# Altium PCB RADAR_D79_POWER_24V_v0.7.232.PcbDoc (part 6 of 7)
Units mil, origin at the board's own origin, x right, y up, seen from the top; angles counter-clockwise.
Board outline 3110.24 x 3110.24 mil, 8 copper layers (Top Layer, GND1, SIG1, PWR1, PWR2, SIG2, GND2, Bottom Layer), stack 55.2 mil thick; 304 components, 269 nets, 1408 pads, 1367 vias.
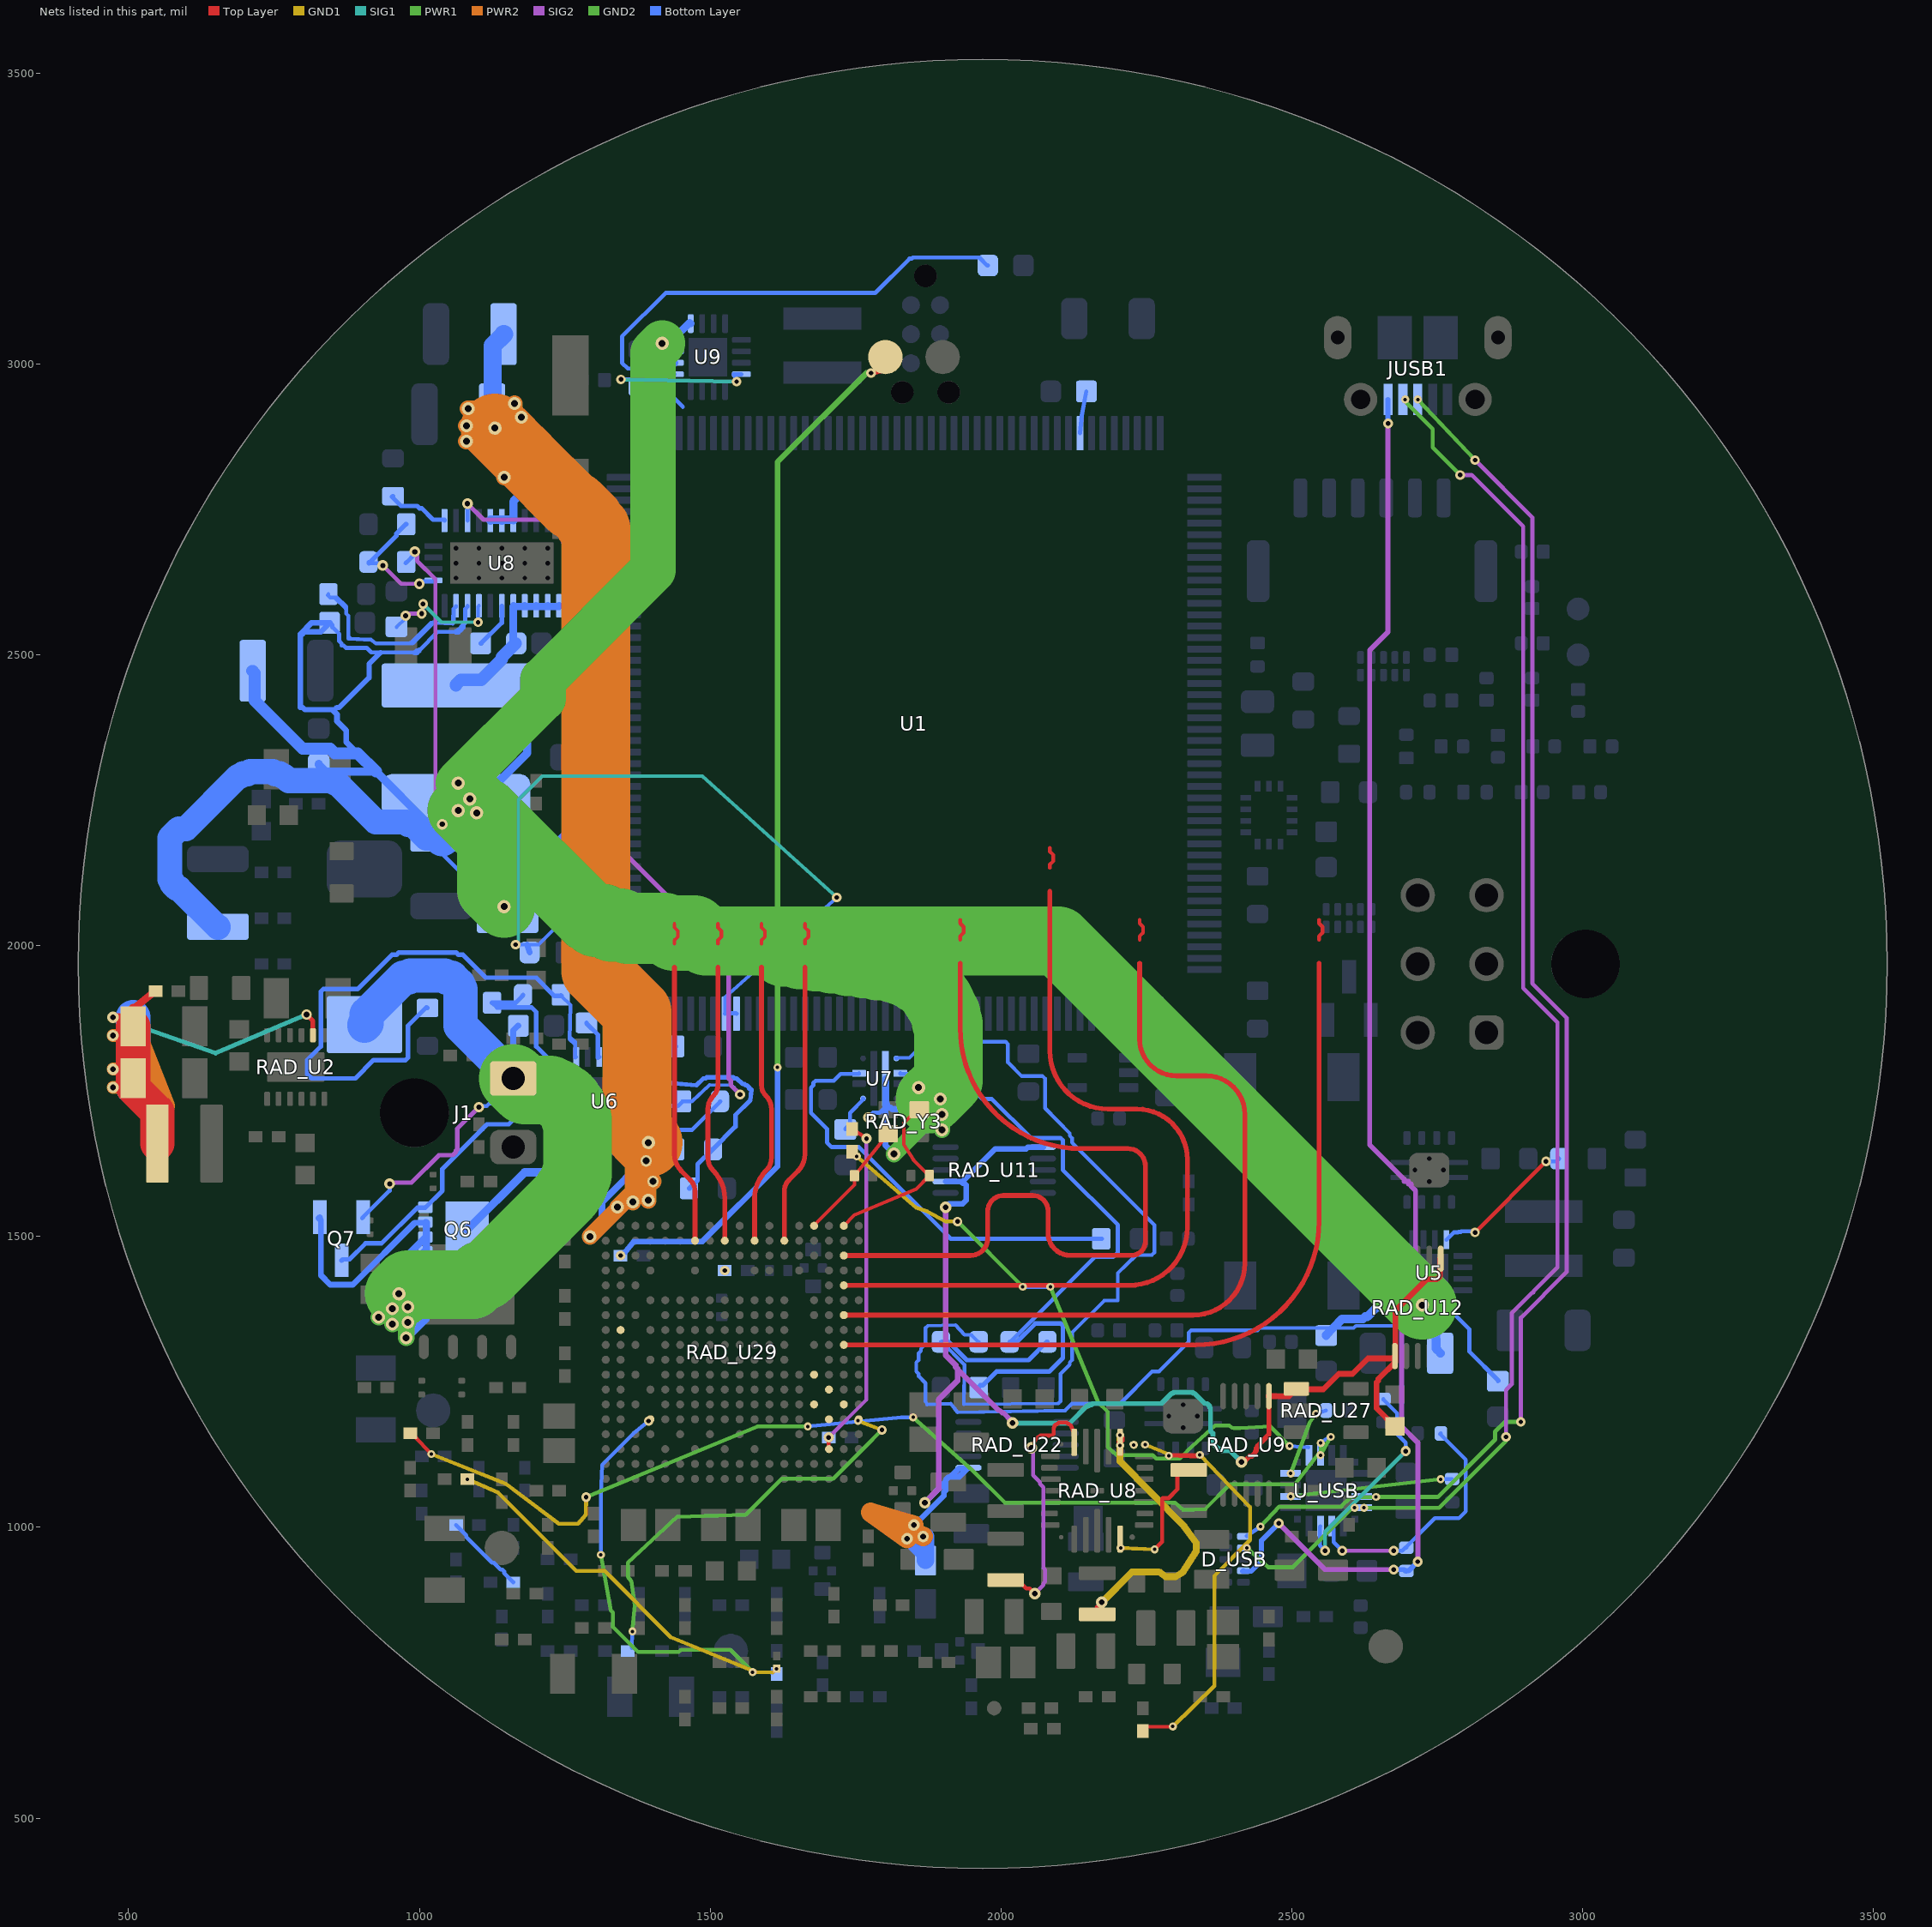
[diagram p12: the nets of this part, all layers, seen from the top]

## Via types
v1: diameter 13.77, hole 5.9, Top Layer to GND1, tented both sides, 393 vias
v2: diameter 16.54, hole 7.87, Top Layer to Bottom Layer, tented both sides, 129 vias
v3: diameter 19.68, hole 9.84, Top Layer to Bottom Layer, tented both sides, 126 vias
v4: diameter 13.77/13.77 (per signal layer), hole 5.9, Top Layer to GND1, tented both sides, 120 vias
v5: diameter 13.77, hole 5.9, Top Layer to GND1, tented top, 104 vias
v6: diameter 13.78, hole 5.91, Top Layer to GND1, tented both sides, 75 vias
v7: diameter 19.68, hole 9.84, Top Layer to Bottom Layer, 74 vias
v8: diameter 17.32, hole 7.87, Top Layer to Bottom Layer, tented both sides, 71 vias
v9: diameter 13.78, hole 5.91, GND2 to Bottom Layer, tented both sides, 64 vias
v10: diameter 13.78, hole 5.91, Top Layer to GND1, tented bottom, 39 vias
v11: diameter 13.78, hole 5.91, GND2 to Bottom Layer, tented top, 38 vias
v12: diameter 13.78, hole 5.91, Top Layer to GND1, 26 vias
v13: diameter 16.54, hole 7.87, GND2 to Bottom Layer, tented both sides, 22 vias
v14: diameter 16.54, hole 7.87, Top Layer to Bottom Layer, 19 vias
v15: diameter 22.05, hole 11.81, Top Layer to Bottom Layer, tented both sides, 17 vias
v16: diameter 13.78, hole 5.91, GND2 to Bottom Layer, 9 vias
v17: diameter 18.11, hole 9.06, Top Layer to Bottom Layer, 7 vias
v18: diameter 22.83, hole 11.81, Top Layer to Bottom Layer, 6 vias
v19: diameter 22.05, hole 11.81, Top Layer to Bottom Layer, 6 vias
v20: diameter 22.83, hole 11.81, Top Layer to Bottom Layer, tented both sides, 5 vias
v21: diameter 19.68, hole 7.87, Top Layer to Bottom Layer, 3 vias
v22: diameter 17.32, hole 8.66, Top Layer to Bottom Layer, 3 vias
v23: diameter 20.47, hole 9.84, Top Layer to Bottom Layer, 3 vias
v24: diameter 17.72, hole 9.84, Top Layer to Bottom Layer, tented both sides, 2 vias
v25: diameter 22.05, hole 11.02, Top Layer to Bottom Layer, 2 vias
v26: diameter 19.68, hole 11.81, Top Layer to Bottom Layer, 2 vias
v27: diameter 18, hole 9.84, Top Layer to Bottom Layer, tented both sides, 1 vias
v28: diameter 18.11, hole 9.06, Top Layer to Bottom Layer, tented both sides, 1 vias

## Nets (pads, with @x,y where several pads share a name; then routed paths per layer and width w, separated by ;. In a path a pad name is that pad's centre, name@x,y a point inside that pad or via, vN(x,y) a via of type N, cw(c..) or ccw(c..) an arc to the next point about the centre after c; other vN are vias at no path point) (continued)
TI_REGOUT_3V3: RAD_C22.2 RAD_C23.1 RAD_C25.1 RAD_C26.1 RAD_C29.1 RAD_C145.1 RAD_L6.2 RAD_R200.1 RAD_U2.8 RAD_U9.6 RAD_U11.2 RAD_U11.6 RAD_U12.1 RAD_U12.6 RAD_U22.6 RAD_U27.1 | length 4299
  Top Layer w8: v27(805.91,1881.42) 816.93,1870.39 RAD_U2.8@816.93,1846.06
  Top Layer w8.66: v3(2413.39,1112.2) 2415.35,1114.17 2419.29,1114.17 2427.17,1122.05 2431.1,1122.05 2437.01,1127.95 2437.01,1129.92 2438.98,1131.89 2438.98,1135.83 2440.94,1137.8 2440.94,1139.76 2460.63,1159.45 RAD_U9.6@2460.63,1225.39 2460.63,1226.38 2460.14,1225.89 RAD_U9.6@2459.65,1225.39
  Top Layer w9.84: RAD_U27.1@2507.87,1238.19 RAD_U27.1@2506.89,1237.2 ; RAD_U12.6@2677.17,1294.29 RAD_U12.6@2678.15,1293.31 ; RAD_U12.1@2755.91,1461.61 2754.92,1461.61 2754.92,1432.09 2749.02,1426.18 2731.3,1426.18 2678.15,1373.03 RAD_U12.6@2678.15,1293.31 ; RAD_U9.6@2460.63,1225.39 2459.65,1225.39 RAD_U9.6@2460.63,1225.39 ; RAD_U9.6@2460.63,1225.39 2495.08,1225.39 RAD_U27.1@2506.89,1237.2 ; RAD_U27.1@2506.89,1237.2 2554.13,1237.2 2580.71,1263.78 2604.33,1263.78 2630.91,1290.35 2675.2,1290.35 RAD_U12.6@2678.15,1293.31 ; RAD_C145.1@2677.17,1173.23 2678.15,1172.24 RAD_C145.1@2677.17,1173.23 ; RAD_C145.1@2677.17,1173.23 2645.67,1204.72 2645.67,1249.02 2648.62,1251.97 2648.62,1254.92 2678.15,1284.45 RAD_U12.6@2678.15,1293.31
  Top Layer w12.6: RAD_C25.1@507.82,1891.04 RAD_C22.2@546.28,1921.91
  Top Layer w13.78: v3(473.03,1756.27) RAD_C29.1@507.82,1756.27 ; v3(473.03,1787.76) RAD_C29.1@507.82,1787.76 ; v3(473.03,1845.37) RAD_C25.1@507.82,1845.37 ; v3(473.03,1876.87) RAD_C25.1@507.82,1876.87
  Top Layer w17.72: RAD_C25.1@507.82,1861.12 507.82,1876.87 RAD_C25.1@507.82,1891.04
  Top Layer w59.06: RAD_C25.1@507.82,1861.12 507.82,1845.37 507.82,1787.76 RAD_C29.1@507.82,1772.02 507.82,1756.27 507.82,1756.15 549.41,1714.57 RAD_L6.2@549.41,1659.68
  PWR2 w21.65: v3(473.03,1756.27) 515.75,1756.27 ; v3(473.03,1787.76) 515.75,1787.76 ; v3(473.03,1845.37) 515.75,1845.37
  PWR2 w33.46: 515.75,1756.27 562.99,1724.41 ; 515.75,1787.76 562.99,1724.41 ; 515.75,1845.37 562.99,1724.41 ; v3(1838.58,980.32) 1835.18,982.76 1775.59,1025.59 ; v3(1850.39,1003.94) 1845.81,1005.27 1775.59,1025.59 ; v3(1866.14,984.25) 1845.67,993.6 1844.82,993.98 1775.59,1025.59
  SIG1 w7.87: v3(473.03,1876.87) 649.61,1814.96 v27(805.91,1881.42)
  SIG1 w8.66: v3(2019.68,1179.13) 2118.11,1179.13 2147.64,1208.66 2149.61,1208.66 2151.57,1210.63 2155.51,1210.63 2157.48,1212.6 2275.59,1212.6 2293.31,1230.32 2295.28,1230.32 2297.24,1232.28 2328.74,1232.28 2330.71,1230.32 2332.68,1230.32 2350.39,1212.6 2354.33,1212.6 2358.27,1208.66 2358.27,1206.69 2360.24,1204.72 2360.24,1165.35 2364.17,1161.42 2364.17,1145.67 2366.14,1143.7 2366.14,1141.73 2372.05,1135.83 2374.02,1135.83 2375.98,1133.86 2377.95,1133.86 2379.92,1131.89 2393.7,1131.89 v3(2413.39,1112.2)
  SIG2 w8.66: 1922.24,1275.59 1921.26,1275.59 1925.2,1271.65 1996.06,1200.79 1998.03,1200.79 2001.97,1196.85 2003.94,1196.85 2017.72,1183.07 2017.72,1181.1 v3(2019.68,1179.13)
  SIG2 w9.84: v7(1869.09,1042.32) 1892.72,1065.94 1892.72,1219.49 1925.2,1251.97 1925.2,1271.65 1925.2,1272.64 1922.24,1275.59 1922.24,1278.54 1904.53,1296.26 v7(1904.53,1550.2)
  Bottom Layer w9.84: v3(1850.39,1003.94) 1851.38,1003.94 1879.43,1031.99 1901.57,1054.13 1901.57,1060.04 1904.53,1062.99 1904.53,1077.76 ; v7(1869.09,1042.32) 1904.53,1077.76 ; v7(1904.53,1550.2) 1910.43,1556.1 1934.06,1556.1 1939.96,1562.01 1939.96,1588.58 1937.01,1591.54 1934.06,1591.54 1931.1,1594.49 ; RAD_U11.2@1904.53,1594.49 1931.1,1594.49 ; RAD_U22.6@1943.9,1102.36 RAD_U22.6@1942.91,1101.38 ; 1904.53,1077.76 1904.53,1080.71 1910.43,1086.61 1913.39,1086.61 ; 1913.39,1086.61 1928.15,1086.61 RAD_U22.6@1942.91,1101.38 ; 1913.39,1086.61 1928.15,1101.38 RAD_U22.6@1942.91,1101.38 ; 1931.1,1594.49 1934.06,1594.49 1990.16,1650.59 2043.31,1650.59 2046.26,1653.54 RAD_U11.6@2071.85,1653.54 ; RAD_U11.6@2071.85,1653.54 2072.83,1653.54 RAD_U11.6@2071.85,1653.54
  Bottom Layer w13.78: v3(473.03,1756.27) RAD_C26.1@507.82,1756.27 ; v3(473.03,1787.76) RAD_C26.1@507.82,1787.76 ; v3(473.03,1845.37) RAD_C23.1@507.82,1845.37 ; v3(473.03,1876.87) RAD_C23.1@507.82,1876.87
  Bottom Layer w21.65: v3(1838.58,980.32) RAD_R200.1@1870.08,948.82 ; v3(1850.39,1003.94) v3@1870.08,984.25 ; v3(1866.14,984.25) v3@1870.08,980.32
  Bottom Layer w29.53: RAD_R200.1@1870.08,942.91 1870.08,948.82 1870.08,980.32 v3@1870.08,984.25
  Bottom Layer w59.06: RAD_C26.1@507.82,1756.27 RAD_C26.1@507.82,1772.02 507.82,1787.76 507.82,1845.37 RAD_C23.1@507.82,1861.12 RAD_C23.1@507.82,1876.87
TI_RX1: RAD_U29.M2 | length 520.8
  Top Layer w6.3: 1438.41,2003.15 1438.41,2009.25 1444.32,2015.16 1444.32,2025.4 1438.41,2031.3 1438.41,2037.4
  Top Layer w8.4: 1438.41,1962.6 1438.41,1850.21 1438.41,1849.22 1438.41,1641.36 ccw(c1479.21,1641.36) 1450.36,1612.51 1465.86,1597.01 cw(c1446.59,1577.74) 1473.85,1577.74 RAD_U29.M2@1473.85,1492.7
TI_RX2: RAD_U29.K2 | length 521.4
  Top Layer w6.3: 1513.22,2003.15 1513.22,2009.25 1519.12,2015.16 1519.12,2025.4 1513.22,2031.3 1513.22,2037.4
  Top Layer w8.4: 1513.22,1962.6 1513.22,1850.21 1513.22,1849.22 1513.22,1760.27 cw(c1487.73,1760.27) 1505.75,1742.24 ccw(c1529.41,1718.59) 1495.95,1718.59 1495.95,1635.46 ccw(c1527.78,1635.46) 1505.27,1612.96 cw(c1457.59,1565.27) 1525.03,1565.27 RAD_U29.K2@1525.03,1492.7
TI_RX3: RAD_U29.H2 | length 521.4
  Top Layer w6.3: 1588.02,2003.15 1588.02,2009.25 1593.93,2015.16 1593.93,2025.4 1588.02,2031.3 1588.02,2037.4
  Top Layer w8.4: RAD_U29.H2@1576.21,1492.7 1576.21,1565.27 cw(c1643.65,1565.27) 1595.96,1612.96 ccw(c1573.46,1635.46) 1605.28,1635.46 1605.28,1718.59 ccw(c1571.83,1718.59) 1595.49,1742.24 cw(c1613.51,1760.27) 1588.02,1760.27 1588.02,1849.22 1588.02,1850.21 1588.02,1962.6
TI_RX4: RAD_U29.F2 | length 520.8
  Top Layer w6.3: 1662.82,2003.15 1662.82,2009.25 1668.73,2015.16 1668.73,2025.4 1662.82,2031.3 1662.82,2037.4
  Top Layer w8.4: RAD_U29.F2@1627.39,1492.7 1627.39,1577.74 cw(c1654.64,1577.74) 1635.37,1597.01 1650.87,1612.51 ccw(c1622.03,1641.36) 1662.82,1641.36 1662.82,1849.22 1662.82,1850.21 1662.82,1962.6
TI_SOP0_TDO: RAD_R310.1 RAD_R386.1 | length 142.7
  Bottom Layer w7.09: RAD_R310.1@1062.99,1003.94 1080.71,986.22 1080.71,983.27 1125,938.98 1127.95,938.98 1139.76,927.17 1142.72,927.17 1145.67,924.21 1145.67,921.26 1160.43,906.5 RAD_R386.1@1161.42,905.51
TI_SOP1_MSS_SPIB_CS2: RAD_R305.1 RAD_U29.R14 | length 705.9
  GND2 w6.69: v16(1312.01,952.76) 1328.74,857.28 1332.68,853.35 1332.68,828.74 1375.98,785.43 1445.87,785.43 1449.8,789.37 1534.45,789.37 v16(1572.83,750.98)
  Bottom Layer w6.69: v16(1312.01,952.76) 1312.01,1057.09 1313.98,1107.28 1369.09,1162.4 v14(1394.12,1182.67) ; v16(1572.83,750.98) 1604.33,750 1607.88,753.84 RAD_R305.1@1609.06,755.12
TI_SOP2_PMIC_CLK: RAD_R218.2 RAD_R299.1 | length 654.2
  GND1 w6.69: v10(1082.68,1082.68) 1134.84,1060.04 1269.68,925.2 1318.9,925.2 1432.09,811.02 1578.74,750.98 1607.28,750 v10(1614.17,756.69)
TI_SOP3_MSS_UARTB_TX: RAD_R301.1 RAD_U29.A14 | length 722.5
  Top Layer w6.69: RAD_U29.A14@1753.18,1183.45 v10(1753.94,1183.07)
  GND1 w6.69: v10(1753.94,1183.07) v2(1795.28,1167.32)
  GND2 w6.69: v9(1366.14,820.87) 1370.08,866.14 1364.17,907.48 1358.27,915.35 1358.27,938.98 1442.91,1017.72 1561.02,1021.65 1623.03,1083.66 1711.61,1083.66 1763.78,1135.83 v2(1795.28,1167.32)
  Bottom Layer w6.69: RAD_R301.1@1365.35,792.52 v9(1366.14,820.87)
TI_SOP4_MSS_UARTA_TX: RAD_R128.1 RAD_R309.1 RAD_U29.C16 | length 591.8
  Top Layer w6.69: v8(1703.74,1154.53) 1703.74,1133.86 RAD_U29.C16@1704.16,1134.44 ; RAD_R128.1@1744.09,1685.04 v8(1768.7,1668.31)
  SIG2 w6.69: v8(1703.74,1154.53) 1768.7,1219.49 v8(1768.7,1668.31)
TI_SW_B1: RAD_L9.1 RAD_U8.28 | length 440.6
  Top Layer w7.09: RAD_L9.1@2007.87,909.45 2028.54,909.45 2043.31,894.68 2049.21,894.68 v3(2058.07,885.83) ; v3(2052.17,1136.81) 2060.04,1152.56 2067.91,1157.48 2087.6,1157.48 2090.55,1160.43 2090.55,1170.28 2092.52,1175.2 2100.39,1180.12 2112.2,1180.12 2120.08,1175.2 RAD_U8.28@2125.98,1160.62 ; RAD_U8.28@2125.98,1145.67 RAD_U8.28@2125.98,1146.16
  SIG2 w7.09: v3(2052.17,1136.81) 2055.12,1133.86 2055.12,1089.57 2066.93,1077.76 2066.93,1074.8 2072.83,1068.9 2072.83,930.12 2075.79,927.17 2075.79,906.5 2072.83,903.54 2072.83,900.59 v3(2058.07,885.83)
TI_SW_B2: RAD_L8.1 RAD_U8.24 | length 501.8
  Top Layer w7.09: RAD_L8.1@2165.35,850.39 2164.37,850.39 2164.37,862.2 v3(2173.23,871.06) ; RAD_U8.24@2204.72,1146.16 2205.71,1145.67 2208.66,1148.62 RAD_U8.24@2208.66,1154.53
  Top Layer w11.81: v12(2204.72,1140.75) RAD_U8.24@2204.72,1146.16
  GND1 w11.81: v3(2173.23,871.06) 2225.39,923.23 2270.67,923.23 2273.62,922.24 2282.48,915.35 2300.2,915.35 2312.01,922.24 2335.63,958.66 2335.63,972.44 2334.65,974.41 2313.98,1002.95 2204.72,1113.19 v12(2204.72,1140.75) v12(2204.72,1158.46)
TI_SW_B3: RAD_L2.1 RAD_U8.14 | length 257.2
  Top Layer w7.09: RAD_U8.14@2204.72,979.82 2204.72,962 v12(2205.71,964.57) ; v12(2264,962) 2277,975 2277,1049 2278,1050 2288,1050 2303,1065 2303,1098.43 RAD_L2.1@2322.83,1098.43
  GND1 w7.09: v12(2205.71,964.57) v12(2264,962)
TI_SYNCCLKIN: RAD_R75.2 RAD_U8.23 | length 779.7
  Top Layer w6.69: RAD_U8.23@2225.63,1142.85 v6(2228.35,1141.73) ; RAD_R75.2@2238.98,656.69 2243.99,656.76 v6(2295.28,657.48) ; v12(2288.39,1123.03) v6@2341.62,1121.2 ; v12@2291.34,1124.41 v6(2341.73,1124.41)
  Top Layer w7.09: RAD_R75.2@2238.98,656.69 2244.09,656.69 RAD_R75.2@2244.09,649.61
  GND1 w6.69: v12(2247.7,1142.22) 2289.29,1125.25 v12@2291.34,1124.41 ; v6(2295.28,657.48) 2366.93,727.56 2366.93,916.54 2428.35,977.95 2428.35,1034.65 v6(2341.73,1124.41)
TI_TCK: RAD_U29.C12
TI_TDI: RAD_U29.D13
TI_TMS: RAD_U29.C14
TI_TX1: RAD_U29.B3 | length 1421.1
  Top Layer w6.3: 1929.74,2010.1 1929.74,2016.2 1935.64,2022.11 1935.64,2032.34 1929.74,2038.25 1929.74,2044.35
  Top Layer w8.4: RAD_U29.B3@1729.75,1467.11 1947.25,1467.11 ccw(c1947.25,1496.94) 1977.08,1496.94 1977.08,1543.13 cw(c2004.41,1543.13) 2004.41,1570.46 2054.41,1570.46 cw(c2054.41,1544.11) 2080.76,1544.11 2080.76,1505.64 ccw(c2118.96,1505.64) 2118.96,1467.45 2224.28,1467.45 ccw(c2224.28,1491.29) 2248.12,1491.29 2248.12,1620.82 ccw(c2217.95,1620.82) 2217.95,1651 2136.82,1651 cw(c2136.82,1858.08) 1929.74,1858.08 ; 1929.74,1857.1 1929.74,1858.08 ; 1929.74,1969.55 1929.74,1858.08
TI_TX2: RAD_U29.B5 | length 1420.2
  Top Layer w6.3: 2083.99,2133.53 2083.99,2139.63 2089.9,2145.53 2089.9,2155.77 2083.99,2161.68 2083.99,2167.78
  Top Layer w8.4: RAD_U29.B5@1729.75,1415.93 2220.58,1415.93 ccw(c2220.58,1515.65) 2320.3,1515.65 2320.3,1632.41 ccw(c2233.71,1632.41) 2233.71,1719.01 2183.99,1719.01 cw(c2183.99,1819.01) 2083.99,1819.01 2083.99,1980.52 2083.99,1981.51 2083.99,2092.97
TI_TX3: RAD_U29.B7 | length 1420.4
  Top Layer w6.3: 2238.28,2010.1 2238.28,2016.2 2244.19,2022.11 2244.19,2032.34 2238.28,2038.25 2238.28,2044.35
  Top Layer w8.4: RAD_U29.B7@1729.75,1364.75 2329.91,1364.75 ccw(c2329.91,1453.99) 2419.15,1453.99 2419.15,1710.08 ccw(c2353.05,1710.08) 2353.05,1776.18 2301.52,1776.18 cw(c2301.52,1839.41) 2238.28,1839.41 2238.28,1857.1 2238.28,1858.08 2238.28,1969.55
TI_TX4: RAD_U29.B9 | length 1421.1
  Top Layer w6.3: 2546.82,2010.1 2546.82,2016.2 2552.73,2022.11 2552.73,2032.34 2546.82,2038.25 2546.82,2044.35
  Top Layer w8.4: RAD_U29.B9@1729.75,1313.57 2334.62,1313.57 ccw(c2334.62,1525.77) 2546.82,1525.77 2546.82,1857.1 2546.82,1858.08 2546.82,1969.55
TI_VBGAP: RAD_C180.1 RAD_U29.K4
  other v14: 1525.03,1441.52
TI_VPP_1P7: RAD_C150.2 RAD_P1.1 RAD_U29.U3 | length 1776.7
  Top Layer w9.84: v2(1776.38,2984.25) RAD_P1.1@1792.32,2988.19
  GND2 w9.84: v9(1615.75,1790.55) 1615.75,2831.5 1768.5,2984.25 v2(1776.38,2984.25)
  Bottom Layer w9.84: RAD_C150.2@1352.98,1472.23 1368.5,1491.34 1486.61,1491.34 1615.75,1620.47 v9(1615.75,1790.55)
  other v14: 1345.89,1467.11
TI_VPP_EN: RAD_U29.U8
TI_XDSET_UARTA_RX: RAD_R129.2 U_USB.18 | length 1852.9
  Top Layer w6.69: RAD_R129.2@991.34,1156.3 v6(1020.47,1125.98)
  GND1 w6.69: v6(1020.47,1125.98) 1148.62,1074.8 1240.16,1005.91 1272.64,1005.91 1286.42,1021.65 v2(1286.61,1051.97)
  GND2 w6.69: v2(1286.61,1051.97) 1581.1,1173.23 v9(1667.72,1173.23) ; v9(1848.82,1188.98) 1951.18,1097.64 2006.3,1042.52 2299.21,1042.52 2313.39,1029.92 2351.18,1031.5 2393.7,1074.02 2505.51,1074.02 2546.21,1126.35 2549.61,1130.71 v9(2549.61,1144.88) ; v11(2549.21,1124.02) 2558.22,1140.03 v9(2566.93,1155.51)
  Bottom Layer w6.69: v9(1667.72,1173.23) 1828.35,1188.98 v9(1848.82,1188.98) ; U_USB.18@2548.03,1137.01 v9(2549.61,1144.88) 2564.96,1155.51 v9(2566.93,1155.51)
TI_XDSET_UARTA_TX: RAD_R128.2 U_USB.17 | length 1110
  Top Layer w6.69: RAD_R128.2@1749.21,1638.58 v10(1751.97,1637.8)
  GND1 w6.69: v10(1751.97,1637.8) 1854.33,1549.21 1872.05,1543.31 1905.51,1525.59 v2(1925.2,1525.59)
  GND2 w6.69: v2(1925.2,1525.59) v9(2037.4,1413.39) ; v9(2084.65,1413.39) 2167.32,1214.57 2183.07,1198.82 2183.07,1137.8 2198.82,1124.02 2260.83,1124.02 2266.73,1118.11 2307.09,1118.11 2320.87,1131.89 2368.11,1175.2 2391.73,1175.2 2397.15,1171.26 2400.1,1170.28 2411.42,1170.28 2462.6,1173.23 v9(2496.06,1139.76)
  Bottom Layer w6.69: v9(2037.4,1413.39) v9(2084.65,1413.39) ; v9(2496.06,1139.76) U_USB.17@2528.35,1137.01
TI_XREF_CLK0: RAD_U29.B13
TI_XREF_CLK1: RAD_U29.D11
TI_XTALM: RAD_C108.1 RAD_U29.B1 RAD_Y3.3 | length 315.3
  Top Layer w6: RAD_U29.B1@1729.75,1518.3 1747.05,1536.42 1854.33,1581.69 RAD_C108.1@1876.7,1604.58 1849.41,1631.89 1832.68,1658.46 1832.68,1694.88 1844.49,1706.69 RAD_Y3.3@1859.26,1718.02
TI_XTALP: RAD_C106.1 RAD_U29.D1 RAD_Y3.1 | length 207.6
  Top Layer w6: RAD_U29.D1@1678.57,1518.3 1678.57,1519.47 1747.97,1588.86 RAD_C106.1@1747.97,1604.37 RAD_Y3.1@1806.11,1676.68
U5_PG: R5P.1 U5.4 | length 253.9
  Top Layer w7.09: v2(2814.96,1506.89) v2(2937.01,1628.94)
  Bottom Layer w7.09: U5.4@2765.75,1494.59 2765.75,1494.09 2778.54,1506.89 2785.43,1506.89 2786.42,1507.87 2790.35,1507.87 2791.34,1508.86 2809.06,1508.86 2811.02,1506.89 v2(2814.96,1506.89) ; v2(2937.01,1628.94) 2954.72,1628.94 R5P.1@2959.65,1633.86
U5_SS_LOCAL: C3.1 U5.9 | length 166.2
  Bottom Layer w7.09: U5.9@2765.75,1379.43 2766.73,1378.94 2805.12,1340.55 2805.12,1302.17 2855.32,1251.97 C3.1@2854.33,1250.98
U6_BGATE: Q6.4 Q7.3 U6.3 | length 509
  Bottom Layer w7.87: Q7.3@866.14,1459.15 866.14,1458.66 868.11,1460.63 879.92,1460.63 907.48,1488.19 935.04,1488.19 996.06,1549.21 Q6.4@1009.84,1549.21 ; Q6.4@1010.24,1550 Q6.4@1009.84,1549.21 ; U6.3@1242.62,1722.44 1242.13,1722.44 1226.38,1722.44 1220.47,1716.54 1218.5,1716.54 1216.54,1714.57 1175.2,1714.57 1153.54,1692.91 1116.14,1692.91 1039.37,1616.14 1039.37,1578.74 Q6.4@1009.84,1549.21
U6_DRV: Q7.1 U6.4 | length 459.1
  SIG2 w7.87: v17(948.82,1590.55) 950.79,1592.52 986.22,1592.52 1033.46,1639.76 1057.09,1639.76 1062.99,1645.67 1062.99,1647.64 1064.96,1649.61 1064.96,1685.04 v22(1102.36,1722.44)
  Bottom Layer w6.69: v22(1102.36,1722.44) 1104.33,1724.41 1116.14,1724.41 1120.08,1728.35 1212.6,1728.35 1220.81,1736.55 1236.22,1737.17 1242.13,1742.13 U6.4@1242.62,1742.13
  Bottom Layer w7.09: Q7.1@903.54,1532.97 901.57,1531.5 948.82,1578.74 v17(948.82,1590.55)
U6_DVDT: C6D.1 U6.9 | length 70.7
  Bottom Layer w7.87: C6D.1@1287.4,1867.13 1287.4,1866.14 1307.09,1846.46 1307.09,1807.09 U6.9@1309.06,1808.56
U6_ILIM_LOCAL: R1.1 U6.10 | length 147.1
  Bottom Layer w7.87: U6.10@1328.74,1808.56 1326.77,1807.09 1330.71,1811.02 1330.71,1830.71 1338.58,1838.58 1429.13,1838.58 1440.94,1826.77 R1.1@1439.96,1826.77
U6_IN_BLOCKED: Q6.5 U6.1 U6.2 | length 279.8
  Bottom Layer w13.78: U6.1@1242.62,1683.07 1244.09,1685.04 1244.09,1700.79 U6.2@1242.62,1702.76
  Bottom Layer w14.17: Q6.5@1082.09,1511.81 1082.68,1511.81 1181.1,1610.24 1212.6,1610.24 1232.28,1629.92 1232.28,1673.23 1242.37,1683.32 U6.1@1244.09,1685.04
U6_OVP_LOCAL: R62.2 R63.1 U6.7 | length 1109.7
  Bottom Layer w6.3: R62.2@1243.11,1915.35 1244.09,1913.39 1259.84,1897.64 1258.56,1842.85 1267.72,1834.65 1267.72,1830.71 1267.72,1808.56 1267.72,1807.09 U6.7@1269.68,1808.56
  Bottom Layer w6.69: 1259.84,1897.64 1258.01,1838.92 1267.72,1830.71
  Bottom Layer w7.87: R63.1@1013.78,1892.72 1011.81,1893.7 980.32,1862.2 980.32,1807.09 976.38,1803.15 921.26,1803.15 889.76,1771.65 814.96,1771.65 807.09,1779.53 807.09,1803.15 830.71,1826.77 830.71,1921.26 834.65,1925.2 893.7,1925.2 952.76,1984.25 960.63,1984.25 964.57,1988.19 1062.99,1988.19 1066.93,1984.25 1074.8,1984.25 1114.17,1944.88 1200.79,1944.88 1232.28,1913.39 R62.2@1244.09,1913.39
U6_PGTH_LOCAL: R804.2 R805.1 U6.15 | length 417.4
  Bottom Layer w7.87: U6.15@1395.18,1742.13 1413.39,1742.13 1421.26,1750 1421.26,1751.97 1429.13,1764.13 1476.38,1759.84 1488.19,1771.65 1492.13,1771.65 1494.09,1773.62 1539.37,1773.62 1541.34,1771.65 1545.28,1771.65 1555.59,1762.28 1559.06,1761.81 1561.02,1759.84 1562.99,1759.84 1566.93,1755.91 1566.93,1753.94 1570.87,1751.97 1568.9,1734.25 1543.31,1708.66 1543.31,1688.98 R804.2@1503.94,1649.61 ; R805.1@1463.58,1582.68 1464.57,1582.68 1478.35,1596.46 1478.35,1624.02 R804.2@1503.94,1649.61 ; R804.2@1504.92,1649.61 R804.2@1503.94,1649.61
U6_UVLO_LOCAL: R61.2 R62.1 U6.6 | length 263.3
  Bottom Layer w7.87: R61.2@1125,1901.57 R61.2@1125.98,1901.57 ; R62.1@1178.15,1915.35 1177.17,1913.39 1165.35,1901.57 R61.2@1125.98,1901.57 ; U6.6@1242.62,1781.5 1244.09,1783.46 1200.79,1826.77 1200.79,1885.83 1192.91,1893.7 1133.86,1893.7 R61.2@1125.98,1901.57
U7_DVDT: C7D.1 U7.7 | length 66.6
  Bottom Layer w6.69: C7D.1@1732.28,1684.06 1732.28,1685.04 1740.16,1692.91 1740.16,1712.6 1763.78,1736.22 U7.7@1762.8,1737.2
U7_ILIM_LOCAL: R2.1 U7.9 | length 742.6
  Bottom Layer w7.09: U7.9@1755.91,1780.51 1755.91,1779.53 1724.41,1779.53 1712.6,1767.72 1681.1,1767.72 1677.17,1763.78 1677.17,1759.84 1673.23,1755.91 1673.23,1712.6 1700.79,1685.04 1700.79,1661.42 1708.66,1653.54 1755.91,1653.54 1913.39,1496.06 R2.1@2172.24,1496.06 R2.1@2173.23,1496.06
U7_OVLO_LOCAL: R72.2 R73.1 U7.2 | length 1140.9
  Bottom Layer w7.09: U7.2@1826.77,1780.51 1826.77,1779.53 1866.14,1779.53 1870.08,1783.46 1921.26,1783.46 1968.5,1736.22 1984.25,1736.22 2051.18,1669.29 2102.36,1669.29 2106.3,1665.35 2106.3,1614.17 2200.79,1519.68 2200.79,1472.44 2192.91,1464.57 2161.42,1464.57 2015.75,1318.9 R72.2@2014.76,1318.9
  Bottom Layer w7.87: R73.1@1961.61,1240.16 1960.63,1240.16 1964.57,1244.09 1968.5,1244.09 1992.13,1267.72 2082.68,1267.72 2106.3,1291.34 2106.3,1346.46 2102.36,1350.39 2059.06,1350.39 2027.56,1318.9 R72.2@2015.75,1318.9
U7_UVLO_LOCAL: R71.2 R72.1 U7.1 | length 1543.3
  Bottom Layer w6.3: U7.1@1819.88,1806.1 1818.9,1807.09 1842.52,1807.09 1870.08,1834.65 2007.87,1834.65 2011.81,1830.71 2011.81,1799.21 2035.43,1775.59 2070.87,1775.59 2075.79,1771.65 2075.79,1720.47 2118.11,1677.17 2118.11,1673.23 2122.05,1669.29 2122.05,1661.42 2263.78,1519.68 2263.78,1472.44 2259.84,1468.5 2231.95,1467.7 2200.79,1437.01 2200.79,1389.76 2177.17,1389.29 2122.05,1334.65 2122.05,1287.4 2118.11,1283.46 2118.11,1279.53 2102.36,1263.78 2102.36,1216.54 2098.43,1213.07 1935.95,1211.54 1937.01,1279.53 1897.64,1318.9 R71.2@1896.65,1318.9
  Bottom Layer w7.87: R71.2@1897.64,1318.9 1909.45,1318.9 1940.94,1287.4 2047.24,1287.4 2078.74,1318.9 R72.1@2079.72,1318.9
U8_BOOT: C805.1 U8.6 | length 80.1
  Bottom Layer w7.87: C805.1@1105.32,2519.68 1106.3,2519.68 1141.73,2555.12 U8.6@1141.73,2584.15
U8_ENABLE: R806.1 U6.16 U8.18 | length 1483.6
  SIG2 w7.87: v17(1082.68,2759.84) 1110.24,2732.28 1212.6,2732.28 1216.54,2728.35 1220.47,2728.35 1244.09,2704.72 1244.09,2700.79 1248.03,2696.85 1248.03,2692.91 1251.97,2688.98 1251.97,2590.55 1358.27,2484.25 1358.27,2153.54 1531.5,1980.32 1531.5,1771.65 1535.43,1767.72 1535.43,1759.84 v22(1551.18,1744.09)
  Bottom Layer w6.3: R806.1@1451.77,1732.28 1452.76,1732.28 1468.5,1732.28 1499.09,1760.51 1535.43,1759.84 1541.34,1755.91 1541.34,1753.94 v22(1551.18,1744.09)
  Bottom Layer w7.09: U8.18@1082.68,2730.81 v17(1082.68,2759.84) ; U6.16@1395.18,1722.44 1393.7,1724.41 1395.18,1724.41 1444.88,1724.41 1452.26,1731.79 R806.1@1452.76,1732.28
U8_FB_LOCAL: R800.2 R801.1 U8.12 | length 224.8
  SIG2 w7.09: v17(937.01,2653.54) 968.5,2622.05 v17(1000,2622.05)
  Bottom Layer w7.09: R800.2@912.4,2659.45 913.39,2657.48 933.07,2657.48 v17(937.01,2653.54) ; v17(1000,2622.05) 1003.94,2625.98 1023.62,2625.98 U8.12@1024.11,2627.95
  Bottom Layer w7.87: R800.2@913.39,2657.48 960.63,2704.72 960.63,2708.66 976.38,2724.41 R801.1@977.36,2724.41
U8_PGOOD: R803.1 U8.16 | length 110.5
  Bottom Layer w7.87: R803.1@954.72,2772.64 952.76,2771.65 968.5,2755.91 996.06,2755.91 1000,2751.97 1003.94,2751.97 1023.62,2732.28 1043.31,2732.28 U8.16@1043.31,2730.81
U8_RT_LOCAL: R802.1 U8.10 | length 507
  Bottom Layer w6.3: R802.1@843.5,2604.33 842.52,2602.36 846.46,2598.43 854.33,2598.43 874.02,2578.74 874.02,2570.87 877.95,2566.93 877.95,2531.5 881.89,2527.56 916.99,2525.81 925.2,2519.68 984.25,2519.68 1019.68,2555.12 1023.53,2555.03 1027.04,2554.95 1054.78,2554.31 1057.65,2557.5 1059.06,2559.06 1059.06,2578.74 1062.99,2582.68 U8.10@1062.99,2584.15
  Bottom Layer w7.09: R802.1@854.33,2598.43 858.27,2598.43 874.02,2582.68 874.02,2578.74 ; 877.95,2531.5 877.95,2527.56 916.99,2525.81 ; 984.25,2519.68 988.19,2519.68 1023.53,2555.03 1023.62,2555.12 1027.04,2554.95 1057.38,2553.45 1057.65,2557.5 U8.10@1059.06,2578.74
U8_SW: C805.2 L8.1 U8.1 U8.2 U8.3 U8.4 U8.5 | length 287.3
  Bottom Layer w12.6: U8.5@1161.42,2584.15 1161.42,2582.68 U8.4@1181.1,2582.68 ; U8.4@1181.1,2584.15 U8.4@1181.1,2582.68 ; U8.3@1200.79,2584.15 U8.3@1200.79,2582.68 ; U8.2@1220.47,2584.15 U8.2@1220.47,2582.68 ; U8.1@1240.16,2584.15 1240.16,2582.68 U8.2@1220.47,2582.68 ; U8.4@1181.1,2582.68 U8.3@1200.79,2582.68 ; U8.3@1200.79,2582.68 U8.2@1220.47,2582.68
  Bottom Layer w13.39: U8.5@1161.42,2582.68 1161.42,2523.62 1165.35,2519.68 C805.2@1166.34,2519.68
  Bottom Layer w21.26: L8.1@1062.99,2447.24 1062.99,2448.82 1070.87,2456.69 1106.3,2456.69 1141.73,2492.13 1141.73,2496.06 C805.2@1165.35,2519.68
U8_VCC: C803.1 U8.8 | length 212.1
  SIG1 w6.3: v2(1006.3,2587.4) 1037.8,2555.91 v2(1100.79,2555.91)
  SIG2 w7.48: v17(976.38,2566.93) 980.32,2570.87 v22(1003.94,2570.87)
  Bottom Layer w5.91: C803.1@960.63,2548.23 960.63,2547.24 961.12,2547.74 976.38,2562.99 v17(976.38,2566.93)
  Bottom Layer w6.3: v22(1003.94,2570.87) 1004.72,2570.08 1006.3,2571.65 v2(1006.3,2587.4) ; v2(1100.79,2555.91) 1100.79,2582.68 1102.36,2584.25 U8.8@1102.36,2584.15
U9_PG: R90.1 U9.4 | length 442.3
  SIG1 w7.09: v2(1346.46,2973.43) v2(1545.28,2969.49)
  Bottom Layer w7.09: v2(1346.46,2973.43) 1406.5,2973.43 1452.76,2926.18 1420.28,2958.66 1378.94,2958.66 1377.95,2959 R90.1@1377.95,2959.65 ; v2(1545.28,2969.49) 1542.4,2978.83 1541.34,2982.28 1540,2982.28 U9.4@1553.64,2982.28
U9_SS_LOCAL: C92.1 U9.9 | length 835.4
  Bottom Layer w7.09: U9.9@1438.48,2982.28 1438.98,2982.28 1419.29,2982.28 1409.45,2992.13 1358.27,2992.13 1348.43,3001.97 1348.43,3047.24 1423.23,3122.05 1783.46,3122.05 1842.52,3181.1 1846.46,3181.1 1848.43,3183.07 1962.6,3183.07 1976.38,3169.29 C92.1@1977.36,3169.29
USB_BRIDGE_RESET_N: R_USB_RESET.2 U_USB.9 | length 381
  SIG1 w6.69: v8(2557.09,959.65) 2557.09,992.13 v8(2695.87,1130.91)
  Bottom Layer w6.69: U_USB.9@2549.21,1001.97 2548.23,1000.98 2548.23,968.5 v8(2557.09,959.65) ; R_USB_RESET.2@2657.48,1220.87 2657.48,1219.49 2681.1,1195.87 2681.1,1160.43 2695.87,1145.67 v8(2695.87,1130.91)
USB_CTS_N: R_USB_CTS.2 U_USB.15 | length 130
  GND2 w6.69: v11(2498.03,1092.52) 2530.51,1180.12 v9(2541.34,1194.88)
  Bottom Layer w6.69: v9(2541.34,1194.88) R_USB_CTS.2@2558.66,1200.79
USB_DM: D_USB.2 JUSB1.2 U_USB.5 | length 2480.4
  SIG2 w7.09: v2(2789.37,2809.06) 2809.06,2809.06 2897.64,2720.47 2897.64,1927.17 2956.69,1868.11 2956.69,1446.85 2915.35,1405.51 2915.35,1403.54 2913.39,1403.54 2877.95,1368.11 2877.95,1246.06 2868.11,1236.22 v2(2868.11,1155.51)
  GND2 w7.09: v11(2422.64,964.57) 2459.65,931.1 2500.98,931.1 2603.35,1033.46 v9(2607.81,1033.46) ; v11(2624.02,1033.46) 2752.95,1033.46 2868.11,1148.62 v2(2868.11,1155.51) ; v11(2694.88,2938.98) 2694.88,2935.04 2742.13,2887.8 2742.13,2856.3 v2(2789.37,2809.06)
USB_DP: D_USB.1 JUSB1.3 U_USB.4 | length 2478.2
  SIG2 w7.09: v2(2814.96,2834.65) 2913.39,2736.22 2913.39,1935.04 2972.44,1875.98 2972.44,1438.98 2893.7,1360.24 v2(2893.7,1181.1)
  GND2 w7.09: v9(2445.87,1000.98) 2478.35,1035.43 2584.65,1035.43 2600.39,1051.18 v9(2644.68,1052.17) 2750.98,1052.17 2849.41,1150.59 2849.41,1164.37 2866.14,1181.1 v2(2893.7,1181.1) ; v11(2716.54,2938.98) v2(2814.96,2834.65)
  Bottom Layer w7.09: D_USB.1@2422.64,985.24 v9(2445.87,1000.98) ; U_USB.4@2620.08,1053.15 v9(2644.68,1052.17)
USB_VBUS: D_USB.4 JUSB1.1 R_USB_VBUS_H.1 | length 2471
  SIG2 w8.66: v8(2477.36,1006.89) 2557.09,927.17 v8(2675.2,927.17) ; v8(2665.35,2897.64) 2665.35,2539.37 2633.86,2507.87 2633.86,1657.48 2692.91,1598.43 2692.91,1594.49 2700.79,1594.49 2700.79,1590.55 2704.72,1590.55 2704.72,1586.61 2712.6,1578.74 2712.6,1409.45 2688.98,1385.83 2688.98,1173.23 2716.54,1145.67 v8(2716.54,940.94)
  Bottom Layer w8.66: D_USB.4@2416.73,925.2 2415.35,924.21 2430.12,924.21 2447.83,941.93 2447.83,977.36 v8(2477.36,1006.89) ; v8(2665.35,2897.64) 2665.35,2937.01 JUSB1.1@2665.35,2938.98 ; v8(2675.2,927.17) 2692.91,927.17 2695.87,924.21 2696.85,924.8 2696.85,925.2 2700.79,925.2 v8(2716.54,940.94)
USB_VBUS_SENSE: R_USB_VBUS_H.2 R_USB_VBUS_L.1 U_USB.8 | length 444.5
  SIG2 w6.69: v8(2586.61,959.65) v8(2675.2,959.65)
  Bottom Layer w6.69: U_USB.8@2568.9,1001.97 2568.9,1000.98 2571.85,998.03 2571.85,974.41 v8(2586.61,959.65) ; v8(2675.2,959.65) 2689.96,959.65 R_USB_VBUS_H.2@2695.87,965.55 ; R_USB_VBUS_H.2@2696.85,964.96 R_USB_VBUS_H.2@2695.87,965.55 ; R_USB_VBUS_L.1@2756.3,1161.42 2754.92,1160.43 2755.12,1160.24 2799.21,1116.14 2799.21,1027.56 2787.4,1015.75 2746.06,1015.75 2696.06,965.75 R_USB_VBUS_H.2@2695.87,965.55
USB_WAKE_N: R_USB_WAKE.2 U_USB.13 | length 279.2
  GND2 w6.69: v11(2498.03,1053.15) v9(2755.91,1082.68)
  Bottom Layer w6.69: v9(2755.91,1082.68) R_USB_WAKE.2@2775.59,1083.07
V12_SYS: C1.1 C4.1 C90.1 C93.1 C804.1 C806.1 C807.1 C808.1 C809.1 L8.2 R71.1 R800.1 U5.10 U5.11 U5.12 U5.13 U7.5 U8.9 U9.10 U9.11 U9.12 U9.13 | length 10302.7
  PWR1 w22.83: v18(1858.27,1755.91) 1877.95,1736.22
  PWR1 w28.35: v19(1815.94,1641.73) 1860.24,1686.02 1860.24,1718.5 1877.95,1736.22 ; 1893.7,1751.97 1892.72,1750.98 1895.67,1748.03 v15(1895.67,1736.22) ; v15(1898.62,1683.07) v15(1898.62,1709.65) ; 1877.95,1736.22 1886.81,1727.36 1898.62,1715.55 v15(1898.62,1709.65) ; 1877.95,1736.22 1880.91,1733.27 1880.91,1727.36 v15(1898.62,1709.65)
  PWR1 w78.74: v18(1066.93,2279.53) 1212.6,2425.2 1212.6,2456.69 1401.57,2645.67 1401.57,3019.68 v18(1417.32,3035.43)
  PWR1 w106.3: v20(1066.93,2232.28) 1118.11,2181.1 1118.11,2094.49 v18(1145.67,2066.93)
  PWR1 w118.11: v20(1086.61,2251.97) 1110.24,2228.35 ; v20(1098.43,2228.35) 1110.24,2228.35 ; 1877.95,1736.22 1893.7,1751.97 1909.45,1767.72 1909.45,1866.14 1905.51,1870.08 1905.51,1881.89 1901.57,1885.83 1901.57,1889.76 1897.64,1893.7 1897.64,1897.64 1893.7,1901.57 1893.7,1905.51 1885.83,1913.39 1885.83,1917.32 1862.2,1940.94 1858.27,1940.94 1850.39,1948.82 1846.46,1948.82 1842.52,1952.76 1838.58,1952.76 1834.65,1956.69 1826.77,1956.69 1822.83,1960.63 1814.96,1960.63 1811.02,1964.57 1787.4,1964.57 1783.46,1968.5 1763.78,1968.5 1759.84,1972.44 1736.22,1972.44 1732.28,1976.38 1708.66,1976.38 1704.72,1980.32 1681.1,1980.32 1677.17,1984.25 1653.54,1984.25 1649.61,1988.19 1625.98,1988.19 1606.3,2007.87 ; v20(2724.41,1381.89) 2098.43,2007.87 1606.3,2007.87 ; 1110.24,2228.35 1114.17,2228.35 1295.28,2047.24 ; 1110.24,2228.35 1291.34,2047.24 1295.28,2047.24 ; 1295.28,2047.24 1303.15,2039.37 1322.83,2039.37 ; 1295.28,2047.24 1314.96,2047.24 1322.83,2039.37 ; 1322.83,2039.37 1346.46,2039.37 1354.33,2031.5 ; 1322.83,2039.37 1330.71,2031.5 1354.33,2031.5 ; 1354.33,2031.5 1358.27,2027.56 1425.2,2027.56 ; 1354.33,2031.5 1421.26,2031.5 1425.2,2027.56 ; 1425.2,2027.56 1437.01,2015.75 1484.25,2015.75 ; 1425.2,2027.56 1472.44,2027.56 1484.25,2015.75 ; 1484.25,2015.75 1492.13,2007.87 1606.3,2007.87
  SIG2 w7.09: v17(992.13,2677.17) 996.06,2673.23 996.06,2661.42 1027.56,2629.92 1027.56,2220.47 v28(1039.37,2208.66)
  Bottom Layer w6.3: C806.1@1037.4,2184.06 1039.37,2185.04 1039.37,2157.48 1102.36,2094.49 1102.36,2090.55 1149.61,2043.31 C807.1@1151.57,2044.29 ; R71.1@1961.61,1318.9 1960.63,1318.9 1948.82,1330.71 1937.01,1330.71 1921.59,1347.74 1874.02,1346.46 1870.08,1342.52 1870.08,1314.96 1862.2,1307.09 1862.2,1303.15 1858.27,1299.21 1858.27,1287.4 1854.33,1283.46 1854.33,1267.72 1858.27,1263.78 1858.27,1259.84 1870.08,1248.03 1870.08,1216.54 1872.96,1211.07 1913.39,1212.6 1925.2,1197.44 2110.24,1200.79 2122.05,1212.6 2204.72,1212.6 2259.84,1267.72 2271.65,1267.72 2322.83,1318.9 2322.83,1334.65 2326.77,1338.58 2440.94,1338.58 2444.88,1342.52 2570.87,1342.52 2606.3,1342.52 2610.24,1346.46 2716.54,1346.46 2737.79,1368.36 2747.09,1377.95 U5.10@2746.06,1379.43
  Bottom Layer w7.09: C804.1@845.47,2555.12 846.46,2555.12 850.39,2551.18 850.39,2547.24 862.2,2535.43 862.2,2523.62 866.14,2519.68 866.14,2515.75 870.08,2515.75 874.02,2511.81 909.45,2511.81 917.32,2503.94 933.07,2503.94 992.13,2503.94 996.06,2507.87 1000,2507.87 1031.5,2539.37 1062.99,2539.37 1066.93,2543.31 1070.87,2543.31 1070.87,2547.24 1074.8,2551.18 1078.74,2555.12 1078.74,2578.74 1082.68,2582.68 U8.9@1082.68,2584.15 ; R800.1@977.36,2659.45 976.38,2657.48 992.13,2673.23 v17(992.13,2677.17) ; C806.1@1039.37,2185.04 v28(1039.37,2208.66) ; v17(1771.65,1704.72) 1779.53,1712.6 1791.34,1712.6 1799.21,1720.47 1800.32,1771.65 U7.5@1801.18,1771.65
  Bottom Layer w8.66: L8.2@1062.99,2257.48 1062.99,2255.91 1082.68,2255.91 v20(1086.61,2251.97) ; U7.5@1800.32,1771.65 1800.61,1771.24 1801.18,1770.45 1803.15,1767.72 1803.15,1728.35 1803.15,1724.41 1807.09,1720.47 1811.02,1720.47 1830.71,1720.47 1834.65,1724.41 1834.65,1732.28 v18(1858.27,1755.91)
  Bottom Layer w9.06: C804.1@846.46,2555.12 830.71,2539.37 803.15,2539.37 799.21,2535.43 795.28,2535.43 795.28,2409.45 799.21,2409.45 803.15,2405.51 850.39,2405.51 854.33,2405.51 858.27,2409.45 862.2,2409.45 913.39,2460.63 913.39,2484.25 933.07,2503.94 ; 992.13,2503.94 996.06,2503.94 1000,2507.87 ; 1062.99,2539.37 1066.93,2539.37 1070.87,2543.31 1074.8,2547.24 1074.8,2551.18
  Bottom Layer w9.84: 795.28,2535.43 814.96,2555.12 C804.1@845.47,2555.12 ; 850.39,2405.51 858.27,2397.64 858.27,2385.83 874.02,2370.08 874.02,2350.39 893.7,2330.71 925.2,2299.21 1014.96,2209.45 1038.88,2185.53 C806.1@1039.37,2185.04
  Bottom Layer w10.24: U7.5@1801.18,1771.65 1801.18,1770.45 U7.5@1801.18,1730.32 ; v19(1815.94,1641.73) 1801.18,1656.5 U7.5@1801.18,1730.32 ; v15(1895.67,1736.22) 1877.95,1718.5 ; v15(1898.62,1683.07) 1863.19,1718.5 ; v15(1898.62,1709.65) 1889.76,1718.5 1877.95,1718.5 ; U7.5@1801.18,1730.32 1803.15,1728.35 1804.13,1727.36 1804.13,1724.41 1807.09,1721.46 1810.04,1721.46 1811.02,1720.47 1812.99,1718.5 1863.19,1718.5 ; 1863.19,1718.5 1877.95,1718.5
  Bottom Layer w12.6: U9.10@1438.48,3001.97 1437.01,3000 U9.11@1437.01,3019.68 ; U9.11@1438.48,3021.65 U9.11@1437.01,3019.68 ; U9.12@1438.48,3041.34 U9.12@1437.01,3043.31 ; U9.13@1466.54,3069.39 1464.57,3070.87 U9.12@1437.01,3043.31 ; U5.13@2678.64,1407.48 2677.17,1405.51 U5.12@2704.72,1377.95 ; U5.12@2706.69,1379.43 U5.12@2704.72,1377.95 ; U5.11@2726.38,1379.43 U5.11@2728.35,1377.95 ; U5.10@2747.09,1377.95 2746.06,1377.95 U5.11@2728.35,1377.95 ; U9.11@1437.01,3019.68 1437.01,3041.34 U9.12@1437.01,3043.31 ; U5.12@2704.72,1377.95 2706.69,1377.95 2724.41,1377.95 2726.38,1377.95 U5.11@2728.35,1377.95
  Bottom Layer w14.17: C93.1@826.77,2312.01 826.77,2311.02 838.58,2299.21 925.2,2299.21 1014.96,2209.45 C806.1@1038.88,2185.53 ; C806.1@1039.37,2185.04 1062.99,2208.66 1086.61,2232.28 1185.04,2330.71 1185.04,2362.2 1255.91,2433.07 1255.91,2437.01 1259.84,2440.94 C90.1@1259.84,2439.96
  Bottom Layer w14.57: L8.2@1062.99,2257.48 1062.99,2275.59 v18(1066.93,2279.53) ; v18(1417.32,3035.43) 1421.26,3035.43 U9.11@1437.01,3019.68
  Bottom Layer w14.96: L8.2@1062.99,2255.91 1076.77,2242.13 1086.61,2232.28 1094.49,2232.28 v20(1098.43,2228.35) ; C4.1@2559.06,1329.72 2559.06,1330.71 2570.87,1342.52 2586.61,1358.27 2622.05,1358.27 2625.98,1362.2 2629.92,1362.2 2645.67,1377.95 U5.12@2704.72,1377.95 ; v20(2724.41,1381.89) 2726.62,1379.68 U5.11@2728.35,1377.95 ; U5.10@2747.09,1377.95 2748.03,1307.09 2755.91,1299.21 C1.1@2754.92,1299.21
  Bottom Layer w20.47: C808.1@713.58,2472.44 712.6,2472.44 716.54,2468.5 716.54,2421.26 799.21,2338.58 846.46,2338.58 854.33,2330.71 893.7,2330.71 925.2,2299.21 ; 1014.96,2209.45 C806.1@1038.88,2185.53
  Bottom Layer w25.59: L8.2@1062.99,2255.91 1062.99,2251.97 1062.99,2236.22 v20(1066.93,2232.28) ; v18(1145.67,2066.93) 1149.61,2062.99 C807.1@1149.61,2043.31
  Bottom Layer w43.31: C809.1@653.54,2032.48 653.54,2031.5 586.61,2098.43 582.68,2098.43 574.8,2106.3 574.8,2110.24 570.87,2114.17 570.87,2185.04 586.61,2200.79 598.43,2200.79 688.98,2291.34 692.91,2291.34 696.85,2295.28 704.72,2295.28 708.66,2299.21 748.03,2299.21 751.97,2295.28 759.84,2295.28 763.78,2291.34 767.72,2291.34 775.59,2283.46 850.39,2283.46 854.33,2279.53 858.27,2279.53 925.2,2212.6 976.38,2212.6 980.32,2208.66 988.19,2208.66 1011.81,2185.04 C806.1@1039.37,2185.04
  Bottom Layer w62.99: C806.1@1039.37,2185.04 1062.99,2208.66 L8.2@1062.99,2236.22
VCAP1_LOCAL: C10.1 U1.81 | length 207.2
  Bottom Layer w7.09: U1.81@1351.38,2667.32 1352.36,2666.34 1316.93,2666.34 1313.98,2663.39 1311.02,2663.39 1311.02,2625 1308.07,2622.05 1308.07,2557.09 C10.1@1270.67,2519.68 ; C10.1@1270.67,2519.68 1269.68,2518.7 C10.1@1270.67,2519.68
VCAP2_LOCAL: C11.1 U1.125 | length 72.7
  Bottom Layer w7.09: U1.125@2135.83,2880.91 2138.78,2911.42 C11.1@2146.65,2952.76
VDDA_FILTERED: C13.1 C14.1 FB1.2 U1.38 U1.39 | length 1492.1
  SIG1 w6.3: v2(1165.35,2001.57) 1170.08,2006.3 1170.08,2250.39 1211.02,2291.34 1486.61,2291.34 v2(1717.52,2082.68)
  Bottom Layer w6.3: v2(1165.35,2001.57) 1185.04,2001.57 1204.72,2001.57 1259.84,2056.69 C14.1@1259.84,2056.1 ; U1.39@1525.59,1882.87 1525.98,1883.46 1525.98,1911.81 v2(1717.52,2082.68)
  Bottom Layer w7.09: U1.39@1525.59,1882.87 1526.57,1883.86 1544.29,1883.86 U1.38@1545.28,1882.87
  Bottom Layer w9.84: FB1.2@1185.04,2001.57 FB1.2@1189.47,1988.19 ; C14.1@1259.84,2067.52 1229.33,2099.41 1229.33,2130.91 1237.2,2180.12 C13.1@1259.84,2203.94
VIN_PROTECTED_24V: C800.1 C801.1 C802.1 R804.1 R806.2 U6.17 U6.18 U8.20 U8.21 U8.22 | length 3645.2
  PWR2 w28.35: v15(1080.71,2867.13) 1107.28,2867.13 v18(1129.92,2889.76) v18@1130.91,2890.75 ; v15(1080.71,2893.7) v18@1127.95,2893.7 ; v19(1083.66,2923.23) 1098.43,2923.23 v18@1127.95,2893.7 ; v19(1145.67,2805.12) 1145.67,2816.93 1174.21,2845.47 1175.2,2846.46 1174.54,2845.14 ; 1152.23,2867.45 1151.57,2867.13 1152.07,2867.62 1175.2,2890.75 v15(1175.2,2908.46) ; v15(1163.39,2932.09) 1163.39,2923.23 v18@1130.91,2890.75 ; v19(1293.31,1500) 1367.13,1573.82 ; v19(1340.55,1550.2) 1367.13,1576.77 ; v15(1367.13,1559.06) 1367.13,1573.82 ; v15(1393.7,1562.01) 1393.7,1595.47 1393.7,1596.46 1393.7,1628.94 1393.7,1629.92 v18(1393.7,1661.42) 1393.7,1662.4 1393.21,1661.91 v18@1390.75,1659.45 ; v18@1127.95,2893.7 v18@1130.91,2890.75 ; v18@1127.95,2893.7 v18@1130.91,2890.75 ; 1367.13,1573.82 1367.13,1576.77 ; 1367.13,1573.82 1378.94,1585.63 1378.94,1588.58 ; 1367.13,1576.77 1367.13,1635.83 1378.94,1647.64 ; 1367.13,1576.77 1378.94,1588.58 ; 1378.94,1588.58 1378.94,1594.49 1378.94,1629.92 1378.94,1641.73 ; 1378.94,1641.73 1378.94,1647.64 ; 1378.94,1641.73 1390.75,1653.54 v18@1390.75,1659.45 ; 1378.94,1647.64 v18@1390.75,1659.45
  PWR2 w29.53: v26(1389.76,1629.92) v26@1393.7,1629.92 ; v26@1393.7,1596.46 1395.67,1594.49 v26(1401.57,1594.49)
  PWR2 w118.11: v18(1129.92,2889.76) 1143.21,2876.48 1152.07,2867.62 1152.23,2867.45 1174.21,2845.47 1174.54,2845.14 1180.12,2839.57 1263.78,2755.91 1267.72,2755.91 1291.34,2732.28 1291.34,2728.35 1303.15,2716.54 1303.15,1956.69 1374.02,1885.83 1374.02,1688.98 1377.95,1685.04 1377.95,1677.17 1393.21,1661.91 v18(1393.7,1661.42)
  Bottom Layer w7.09: R804.1@1439.96,1649.61 1405.51,1649.61 1395.67,1659.45 v18(1393.7,1661.42) 1395.67,1663.39 1399.61,1663.39 1407.23,1671.01 1419.29,1683.07 1468.5,1683.07 1517.72,1732.28 R806.2@1516.73,1732.28
  Bottom Layer w11.81: C800.1@1125,2913.39 1125.98,2913.39 1125.98,2893.7 v18(1129.92,2889.76) ; v19(1293.31,1500) 1296.26,1502.95 1296.26,1508.86 1313.98,1526.57 1313.98,1559.06 v26@1393.7,1638.78 ; v19(1340.55,1550.2) 1393.7,1603.35 ; v15(1367.13,1559.06) 1393.7,1585.63 ; v26(1389.76,1629.92) v26@1393.7,1633.86 ; v15(1393.7,1562.01) 1393.7,1585.63 ; v26(1401.57,1594.49) 1395.67,1600.39 v26@1395.67,1635.83 ; 1393.7,1585.63 1393.7,1594.49 1393.7,1603.35 ; 1393.7,1603.35 1393.7,1629.92 v26@1393.7,1633.86 ; v26@1393.7,1633.86 v26@1395.67,1635.83 ; v26@1393.7,1633.86 v26@1393.7,1638.78 ; v26@1393.7,1638.78 v18(1393.7,1661.42) U6.18@1393.7,1683.07 ; U6.18@1393.7,1683.07 U6.18@1393.7,1685.04 ; U6.18@1393.7,1683.07 U6.18@1395.18,1683.07 ; U6.18@1393.7,1685.04 1393.7,1700.79 1393.7,1702.76 1393.7,1703.74 U6.17@1395.18,1702.76 1395.67,1702.76 U6.18@1395.67,1683.07 ; U6.18@1393.7,1685.04 U6.18@1395.18,1683.07 ; U6.18@1395.18,1683.07 U6.18@1395.67,1683.07 ; v26@1395.67,1635.83 1395.67,1659.45 1395.67,1661.42 1395.67,1663.39 U6.18@1395.67,1683.07
  Bottom Layer w13.78: U8.22@1161.42,2730.81 1161.42,2732.28 1161.42,2763.78 1181.1,2783.46 C802.1@1181.1,2784.45 ; U6.17@1393.7,1700.79 U6.17@1395.18,1702.76
  Bottom Layer w14.96: U8.20@1122.05,2730.81 1122.05,2732.28 U8.21@1141.73,2732.28 ; U8.21@1141.73,2730.81 U8.21@1141.73,2732.28 ; U8.22@1161.42,2732.28 U8.21@1141.73,2732.28
  Bottom Layer w21.65: v15(1080.71,2867.13) 1089.57,2875.98 1089.57,2878.94 C800.1@1125,2914.37 ; v15(1080.71,2893.7) 1101.38,2914.37 ; v19(1083.66,2923.23) 1092.52,2914.37 1101.38,2914.37 ; C800.1@1125,2913.39 C800.1@1125,2914.37 ; C800.1@1125.98,2913.39 1133.86,2905.51 1133.86,2826.77 1149.61,2811.02 1153.54,2811.02 1162.4,2802.17 ; v19(1145.67,2805.12) 1148.62,2802.17 1162.4,2802.17 ; v15(1163.39,2932.09) 1142.72,2932.09 1125.98,2915.35 C800.1@1125,2914.37 ; v15(1175.2,2908.46) 1169.29,2914.37 1125.98,2914.37 C800.1@1125,2914.37 ; C802.1@1181.1,2783.46 1180.61,2783.96 1162.4,2802.17 ; C802.1@1181.1,2784.45 1163.39,2802.17 1162.4,2802.17 ; 1101.38,2914.37 C800.1@1125,2914.37
  Bottom Layer w31.5: C800.1@1125.98,2913.39 1125.98,2914.37 1125.98,2915.35 1125.98,3031.5 1145.67,3051.18 C801.1@1144.69,3051.18
VIN_RAW: C6I.1 D1.1 J1.1 Q6.1 Q6.2 Q6.3 Q7.2 R61.1 U6.5 | length 2653.6
  PWR1 w28.35: v15(930.12,1361.22) 936.02,1367.13 949.31,1380.41 v15@953.74,1384.84 ; v15(953.74,1349.41) v15(953.74,1375.98) v15@953.74,1384.84 ; v15(977.36,1325.79) 977.36,1352.36 977.36,1390.75 v20@965.55,1402.56 ; v15(980.32,1352.36) v15(980.32,1378.94) 980.32,1387.8 v20@965.55,1402.56 ; v15@953.74,1384.84 965.55,1396.65 v20@965.55,1402.56 ; v15@953.74,1384.84 953.74,1390.75 v20(964.57,1401.57) ; v20(964.57,1401.57) 965.13,1402.14 v20@965.55,1402.56 ; v20(964.57,1401.57) v20@965.55,1402.56
  PWR1 w118.11: v20@965.55,1402.56 980.32,1417.32 1090.55,1417.32 1106.3,1433.07 1114.17,1433.07 1255.91,1574.8 1255.91,1578.74 1263.78,1586.61 1263.78,1590.55 1267.72,1594.49 1267.72,1602.36 1271.65,1606.3 1271.65,1700.79 1267.72,1704.72 1267.72,1712.6 1263.78,1716.54 1263.78,1720.47 1255.91,1728.35 1255.91,1732.28 1251.97,1736.22 1248.03,1736.22 1240.16,1744.09 1236.22,1744.09 1232.28,1748.03 1228.35,1748.03 1224.41,1751.97 1181.1,1751.97 J1.1@1161.42,1771.65
  Bottom Layer w9.84: R61.1@1060.04,1901.57 1059.06,1901.57 1070.87,1889.76 1094.49,1866.14 1094.49,1838.58 J1.1@1161.42,1771.65
  Bottom Layer w10.24: Q7.2@828.74,1532.97 826.77,1531.5 830.71,1527.56 830.71,1433.07 846.46,1417.32 885.83,1417.32 992.13,1523.62 1011.81,1523.62 1010.33,1524.73 Q6.3@1010.24,1524.8
  Bottom Layer w10.63: J1.1@1161.42,1771.65 1161.42,1854.33 1169.29,1862.2 C6I.1@1170.28,1862.2
  Bottom Layer w12.2: v20(964.57,1401.57) 964.57,1452.76 1011.81,1500 1010.33,1498.89 Q6.2@1010.24,1498.82
  Bottom Layer w12.6: Q6.1@1010.24,1473.62 1010.33,1473.55 1011.81,1472.44 1011.81,1500 Q6.3@1011.81,1523.62
  Bottom Layer w12.99: J1.1@1161.42,1771.65 1208.66,1771.65 1216.54,1763.78 1244.09,1763.78 U6.5@1242.62,1761.81
  Bottom Layer w14.96: v15(930.12,1361.22) v20@971.46,1402.56 ; v15(953.74,1349.41) 968.5,1364.17 971.46,1367.13 971.46,1375.98 v20@971.46,1393.7 ; v15(953.74,1375.98) v20@971.46,1393.7 ; v15(977.36,1325.79) 1009.84,1358.27 1009.84,1381.89 ; v15(980.32,1352.36) 1009.84,1381.89 ; v15(980.32,1378.94) 1009.84,1408.46 ; Q6.1@1010.24,1473.62 1010.16,1473.58 Q6.1@1009.84,1473.43 ; v20@971.46,1393.7 971.46,1401.57 v20@971.46,1402.56 ; v20@971.46,1402.56 971.46,1435.04 Q6.1@1009.84,1473.43 ; 1009.84,1381.89 1009.84,1408.46 ; 1009.84,1408.46 Q6.1@1009.84,1473.43
  Bottom Layer w59.06: D1.1@905.51,1864.17 905.51,1862.2 909.45,1866.14 909.45,1881.89 972.44,1944.88 980.32,1944.88 984.25,1948.82 1043.31,1948.82 1047.24,1944.88 1055.12,1944.88 1066.93,1933.07 1066.93,1929.13 1070.87,1925.2 1070.87,1889.76 1070.87,1862.2 J1.1@1161.42,1771.65
pads on no net: D3.6 D3.7 D3.9 D3.10 D8.5 D8.6 D8.7 D8.9 D8.10 D_USB.5 D_USB.6 D_USB.7 D_USB.9 D_USB.10 J1.Un1 J6.Un1 J8.5 J8.MP J10.Un1 J10.Un2 J10.Un3 JUSB1.4 JUSB1.7 JUSB1.8 Q6.Un1 Q6.Un2 Q6.Un3 Q6.Un4 Q6.Un5 Q6.Un6 Q6.Un7 Q6.Un8 RAD_U2.11 RAD_U9.3 RAD_U11.3 RAD_U12.3 RAD_U22.3 RAD_U27.4 U1.3 U1.4 U1.5 U1.7 U1.8 U1.9 U1.10 U1.11 U1.12 U1.13 U1.16 U1.17 U1.18 U1.19 U1.20 U1.21 U1.24 U1.25 U1.26 U1.27 U1.28 U1.30 U1.32 U1.33 U1.34 U1.35 U1.41 U1.42 U1.43 U1.44 U1.45 U1.46 U1.47 U1.50 U1.51 U1.52 U1.53 U1.54 U1.55 U1.56 U1.57 U1.58 U1.59 U1.60 U1.63 U1.64 U1.65 U1.66 U1.67 U1.68 U1.69 U1.70 U1.73 U1.74 U1.75 U1.76 U1.77 U1.78 U1.83 U1.84 U1.85 U1.86 U1.87 U1.88 U1.89 U1.98 U1.99 U1.100 U1.101 U1.104 U1.105 U1.106 U1.107 U1.108 U1.109 U1.110 U1.111 U1.112 U1.115 U1.116 U1.117 U1.118 U1.119 U1.122 U1.123 U1.128 U1.129 U1.130 U1.131 U1.132 U1.133 U1.134 U1.138 U1.139 U1.140 U1.141 U1.144 U1.145 U1.146 U1.151 U1.152 U1.153 U1.154 U1.155 U1.156 U1.157 U1.160 U1.162 U1.163 U1.164 U1.165 U1.167 U1.168 U1.169 U1.170 U1.173 U1.174 U1.175 U1.176 U2.2 U2.3 U2.10 U2.11 U4.Un1 U4.Un2 U4.Un3 U4.Un4 U4.Un5 U5.7 U5.8 U5.Un1 U5.Un2 U5.Un3 U5.Un4 U6.12 U6.13 U6.19 U6.20 U6.21 U6.22 U6.23 U6.24 U6.Un1 U6.Un2 U6.Un3 U6.Un4 U7.3 U7.10 U7.Un1 U7.Un2 U7.Un3 U7.Un4 U8.7 U8.11 U8.23 U8.Un1 U8.Un2 U8.Un3 U8.Un4 U8.Un5 U8.Un6 U8.Un7 U8.Un8 U9.7 U9.8 U9.Un1 U9.Un2 U9.Un3 U9.Un4 U_CAN_RAD.Un1 U_CAN_RAD.Un2 U_CAN_RAD.Un3 U_CAN_RAD.Un4 U_CAN_RAD.Un5 U_FRAME.1 U_USB.1 U_USB.2 U_USB.10 U_USB.11 U_USB.14 U_USB.16 U_USB.19 U_USB.20 U_USB.P1 U_USB.P2 U_USB.P3 U_USB.P4 Y1.1

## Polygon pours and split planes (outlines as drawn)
GND on Top Layer "GND_TOP_DIGITAL_RETURN" (solid, remove dead copper, pour order 7): 1141.73,748.03 2066.93,748.03 2066.93,1190.94 1141.73,1190.94
GND on Top Layer "GND_COPLANAR_FEED_REFERENCE" (solid, remove dead copper, pour order 6): 2624.02,1830.71 2624.02,1200.79 1318.9,1200.79 1318.9,1830.71
TI_NetC21_2 on Top Layer "TI_NetC21_2" (solid, remove dead copper, pour order 0): 744.76,1750.23 615.47,1750.23 615.47,1558.2 737.3,1558.2 737.3,1699.8 744.76,1699.8
RADAR_12V on Top Layer "RADAR_12V" (solid, remove dead copper, pour order 1): 812.99,1930.08 748.03,1865.12 748.03,1834.07 665.45,1834.07 665.45,1968.5 812.99,1968.5
GND on Top Layer "GND" (solid, remove dead copper, pour order 2): 812.99,1756.35 598.43,1756.35 598.43,1968.5 640.28,1968.5 640.28,1814.86 812.99,1814.86
GND on GND2 "GND2_REFERENCE" (solid, remove dead copper, pour order 4): 3474.41,1968.5 3472.98,2034.19 3468.68,2099.75 3461.53,2165.06 3451.53,2230 3438.71,2294.44 3423.1,2358.26 3404.71,2421.34 3383.59,2483.55 3359.78,2544.79 3333.32,2604.93 3304.26,2663.85 3272.66,2721.46 3238.57,2777.63 3202.07,2832.26 3163.22,2885.24 3122.09,2936.48 3078.77,2985.88 3033.34,3033.34 2985.88,3078.77 2936.48,3122.09 2885.24,3163.22 2832.26,3202.07 2777.63,3238.57 2721.46,3272.66 2663.85,3304.26 2604.93,3333.32 2544.79,3359.78 2483.55,3383.59 2421.34,3404.71 2358.26,3423.1 2294.44,3438.71 2230,3451.53 2165.06,3461.53 2099.75,3468.68 2034.19,3472.98 1968.5,3474.41 1902.82,3472.98 1837.26,3468.68 1771.94,3461.53 1707.01,3451.53 1642.57,3438.71 1578.75,3423.1 1515.67,3404.71 1453.45,3383.59 1392.22,3359.78 1332.08,3333.32 1273.15,3304.26 1215.55,3272.66 1159.38,3238.57 1104.75,3202.07 1051.77,3163.22 1000.53,3122.09 951.13,3078.77 903.67,3033.34 858.23,2985.88 814.91,2936.48 773.79,2885.24 734.94,2832.26 698.44,2777.63 664.35,2721.46 632.75,2663.85 603.69,2604.93 577.23,2544.79 553.42,2483.55 532.3,2421.34 513.91,2358.26 498.29,2294.44 485.48,2230 475.48,2165.06 468.33,2099.75 464.03,2034.19 462.6,1968.5 464.03,1902.82 468.33,1837.26 475.48,1771.94 485.48,1707.01 498.29,1642.57 513.91,1578.75 532.3,1515.67 553.42,1453.45 577.23,1392.22 603.69,1332.08 632.75,1273.15 664.35,1215.55 698.44,1159.38 734.94,1104.75 773.79,1051.77 814.91,1000.53 858.23,951.13 903.67,903.67 951.13,858.23 1000.53,814.91 1051.77,773.79 1104.75,734.94 1159.38,698.44 1215.55,664.35 1273.15,632.75 1332.08,603.69 1392.22,577.23 1453.45,553.42 1515.67,532.3 1578.75,513.91 1642.57,498.29 1707.01,485.48 1771.94,475.48 1837.26,468.33 1902.82,464.03 1968.5,462.6 2034.19,464.03 2099.75,468.33 2165.06,475.48 2230,485.48 2294.44,498.29 2358.26,513.91 2421.34,532.3 2483.55,553.42 2544.79,577.23 2604.93,603.69 2663.85,632.75 2721.46,664.35 2777.63,698.44 2832.26,734.94 2885.24,773.79 2936.48,814.91 2985.88,858.23 3033.34,903.67 3078.77,951.13 3122.09,1000.53 3163.22,1051.77 3202.07,1104.75 3238.57,1159.38 3272.66,1215.55 3304.26,1273.15 3333.32,1332.08 3359.78,1392.22 3383.59,1453.45 3404.71,1515.67 3423.1,1578.75 3438.71,1642.57 3451.53,1707.01 3461.53,1771.94 3468.68,1837.26 3472.98,1902.82
TI_REGOUT_3V3 on PWR2 "REGOUT_3V3_WINDOW_8" (solid, pour order 8): 1479.33,1128.16 1484.49,1125.52 1489.88,1123.39 1495.45,1121.81 1501.16,1120.77 1506.93,1120.31 1512.73,1120.41 1518.48,1121.07 1524.15,1122.3 1529.66,1124.08 1534.98,1126.39 1540.04,1129.21 1544.81,1132.51 1549.22,1136.26 1553.25,1140.43 1556.85,1144.97 1559.99,1149.84 1562.63,1155 1564.75,1160.39 1566.34,1165.97 1567.37,1171.67 1567.84,1177.44 1567.74,1183.24 1567.08,1189 1565.85,1194.66 1564.07,1200.18 1561.76,1205.49 1558.94,1210.56 1555.64,1215.32 1551.89,1219.73 1547.72,1223.76 1543.18,1227.36 1538.31,1230.5 592.48,1775.58 587.32,1778.22 581.93,1780.35 576.36,1781.93 570.65,1782.97 564.88,1783.43 559.08,1783.34 553.33,1782.67 547.66,1781.44 542.15,1779.66 536.83,1777.35 531.77,1774.53 527,1771.23 522.59,1767.48 518.56,1763.31 514.96,1758.77 511.83,1753.9 509.18,1748.74 507.06,1743.35 505.47,1737.77 504.44,1732.07 503.97,1726.3 504.07,1720.5 504.73,1714.74 505.96,1709.08 507.74,1703.56 510.05,1698.25 512.87,1693.18 516.17,1688.42 519.92,1684.01 524.09,1679.98 528.63,1676.38 533.5,1673.24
